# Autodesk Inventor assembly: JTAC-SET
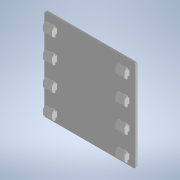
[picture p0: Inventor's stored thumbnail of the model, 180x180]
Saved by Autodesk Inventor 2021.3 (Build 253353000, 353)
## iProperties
Created: 2022-02
Part Number: JTAC-SET
Document SubType Name: Assembly
Designer: kengo
Author: kengo
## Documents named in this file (3)
- C:\Users\kengo\Documents\S2S_frame\SDC345\frame_misumi_ver12\JTAC-SET.iam
- C:\Users\kengo\Documents\S2S_frame\SDC345\frame_misumi_ver12\JTACS-SUD-A170-B170-T4-X17_5-F45-Y17_5-G135-N8-L107_5-V45-S17_5-W135-NA8.ipt
- C:\Users\kengo\Documents\S2S_frame\SDC345\frame_misumi_ver12\CBMHNTT-SET_tuika.iam
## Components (9 placed, 2 different names)
1. JTACS-SUD-A170-B170-T4-X17_5-F45-Y17_5-G135-N8-L107_5-V45-S17_5-W135-NA8:1 — リジッド:1, リジッド:2, リジッド:3, リジッド:4, リジッド:5, リジッド:6, リジッド:7, リジッド:8
2. CBMHNTT-SET_tuika:1 [sub-assembly] — リジッド:1
3. CBMHNTT-SET_tuika:2 [sub-assembly] — リジッド:3
4. CBMHNTT-SET_tuika:3 [sub-assembly] — リジッド:2
5. CBMHNTT-SET_tuika:4 [sub-assembly] — リジッド:7
6. CBMHNTT-SET_tuika:5 [sub-assembly] — リジッド:5
7. CBMHNTT-SET_tuika:6 [sub-assembly] — リジッド:4
8. CBMHNTT-SET_tuika:7 [sub-assembly] — リジッド:8
9. CBMHNTT-SET_tuika:8 [sub-assembly] — リジッド:6
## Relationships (8: WeldJoint 8)
- リジッド:1 [WeldJoint]: JTACS-SUD-A170-B170-T4-X17_5-F45-Y17_5-G135-N8-L107_5-V45-S17_5-W135-NA8:1 ↔ CBMHNTT-SET_tuika:1
- リジッド:2 [WeldJoint]: JTACS-SUD-A170-B170-T4-X17_5-F45-Y17_5-G135-N8-L107_5-V45-S17_5-W135-NA8:1 ↔ CBMHNTT-SET_tuika:3
- リジッド:3 [WeldJoint]: JTACS-SUD-A170-B170-T4-X17_5-F45-Y17_5-G135-N8-L107_5-V45-S17_5-W135-NA8:1 ↔ CBMHNTT-SET_tuika:2
- リジッド:4 [WeldJoint]: JTACS-SUD-A170-B170-T4-X17_5-F45-Y17_5-G135-N8-L107_5-V45-S17_5-W135-NA8:1 ↔ CBMHNTT-SET_tuika:6
- リジッド:5 [WeldJoint]: JTACS-SUD-A170-B170-T4-X17_5-F45-Y17_5-G135-N8-L107_5-V45-S17_5-W135-NA8:1 ↔ CBMHNTT-SET_tuika:5
- リジッド:6 [WeldJoint]: JTACS-SUD-A170-B170-T4-X17_5-F45-Y17_5-G135-N8-L107_5-V45-S17_5-W135-NA8:1 ↔ CBMHNTT-SET_tuika:8
- リジッド:7 [WeldJoint]: JTACS-SUD-A170-B170-T4-X17_5-F45-Y17_5-G135-N8-L107_5-V45-S17_5-W135-NA8:1 ↔ CBMHNTT-SET_tuika:4
- リジッド:8 [WeldJoint]: JTACS-SUD-A170-B170-T4-X17_5-F45-Y17_5-G135-N8-L107_5-V45-S17_5-W135-NA8:1 ↔ CBMHNTT-SET_tuika:7
